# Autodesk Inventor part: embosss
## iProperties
Created: 2009-04
Part Number: embosss
Document SubType Name: Modeling
Designer: Sham
Density: 1 g/cm^3
Author: Sham
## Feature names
1. Extrusion1
2. Extrusion2
